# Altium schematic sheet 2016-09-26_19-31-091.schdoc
size 285 x 139 mm; SheetNumber: 1; SheetTotal: 1
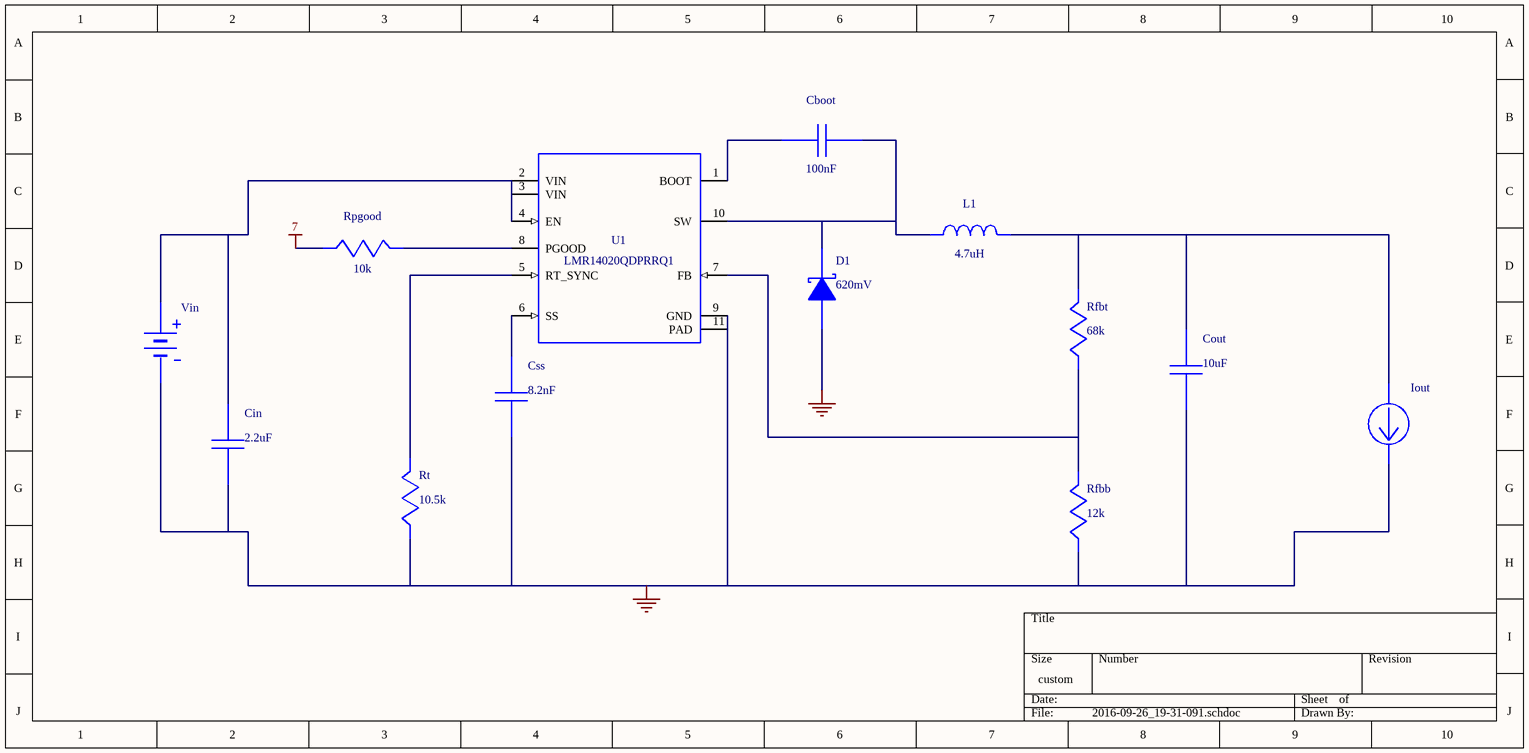
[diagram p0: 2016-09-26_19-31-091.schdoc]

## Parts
Cboot  value 100nF  (hidden comment: C1005X7R1H104K)
Cin  value 2.2uF  (hidden comment: GRM31CR71H225KA88L)
Cout  value 10uF  (hidden comment: GRM188R61C106MA73D)
Css  value 8.2nF  (hidden comment: GRM155R71C822KA01D)
D1  value 620mV  (hidden comment: SS2PH10-M3)
Iout  WB_CURRENT_LOAD  (value not drawn)
L1  value 4.7uH  (hidden comment: XAL4030-472MEB)
Rfbb  value 12k  (hidden comment: RC0603FR-0712KL)
Rfbt  value 68k  (hidden comment: RC0603FR-0768KL)
Rpgood  value 10k  (hidden comment: CRCW040210K0FKED)
Rt  value 10.5k  (hidden comment: CRCW040210K5FKED)
U1  LMR14020QDPRRQ1
Vin  WB_BATTERY  (value not drawn)

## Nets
0: Cin.2 Cout.2 Css.2 D1.2(A) Iout.2(-) Rfbb.2 Rt.2 U1.9(GND) U1.11(PAD) Vin.2(-)
7: Rpgood.2
NetCboot_1: Cboot.1 D1.1(K) L1.1 U1.10(SW)
NetCboot_2: Cboot.2 U1.1(BOOT)
NetCin_1: Cin.1 U1.2(VIN) U1.3(VIN) U1.4(EN) Vin.1(+)
NetCout_1: Cout.1 Iout.1(+) L1.2 Rfbt.1
NetCss_1: Css.1 U1.6(SS)
NetRfbb_1: Rfbb.1 Rfbt.2 U1.7(FB)
NetRpgood_1: Rpgood.1 U1.8(PGOOD)
NetRt_1: Rt.1 U1.5(RT_SYNC)

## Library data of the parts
Cboot = C1005X7R1H104K: Manufacturer Name: TDK
Cin = GRM31CR71H225KA88L: GRM31CR71H225KA8; Manufacturer Name: MuRata
Cout = GRM188R61C106MA73D: GRM188R61C106MA7; Manufacturer Name: MuRata
Css = GRM155R71C822KA01D: GRM155R71C822KA0; Manufacturer Name: MuRata
D1 = SS2PH10-M3: Manufacturer Name: Vishay-Semiconductor
L1 = XAL4030-472MEB: Manufacturer Name: Coilcraft
Rfbb = RC0603FR-0712KL: Manufacturer Name: Yageo America
Rfbt = RC0603FR-0768KL: Manufacturer Name: Yageo America
Rpgood = CRCW040210K0FKED: Manufacturer Name: Vishay-Dale
Rt = CRCW040210K5FKED: Manufacturer Name: Vishay-Dale
U1 = LMR14020QDPRRQ1: Manufacturer Name: Texas Instruments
